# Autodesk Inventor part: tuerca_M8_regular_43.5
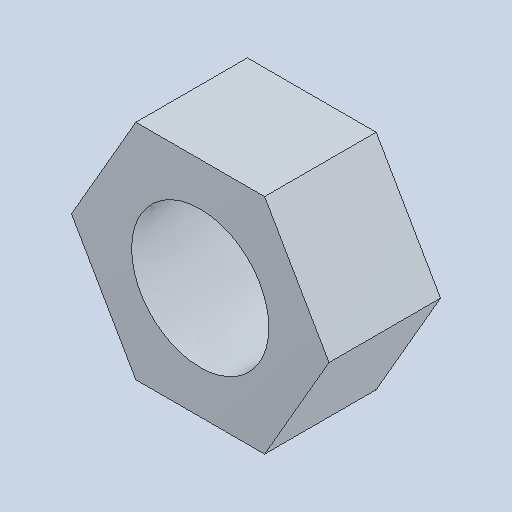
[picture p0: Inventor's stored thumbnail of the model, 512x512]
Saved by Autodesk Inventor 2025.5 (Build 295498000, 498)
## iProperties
Created: 2026-10
Part Number: tuerca_M8_regular_43.5
Material: Genérico
Document SubType Name: Modeling
Designer: Luis M
Density: 1 g/cm^3
Appearance: Valor por defecto
Author: Luis M
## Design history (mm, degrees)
feature "Base1"
node "Sólido1"
